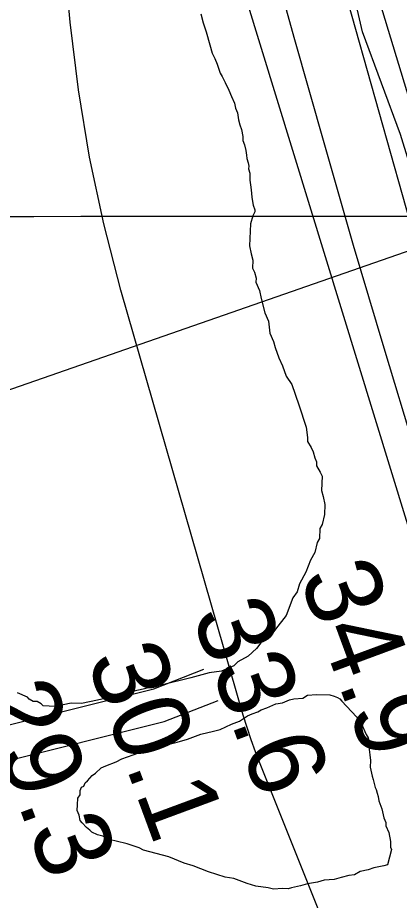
# Model space of a CAD drawing. Extents: x 3297753 to 3335611, y 652252 to 677623.
# Drawn here: x 3307885 to 3308219, y 672189 to 672962 of the extents above; entities that cross this region are included whole.
import ezdxf

# ---------------------------------------------------------------- set-up
doc = ezdxf.new("R2010")
doc.units = 0
for name, color, linetype in [('V-GRID-MAJR', 7, 'Continuous'), ('V-RIVR-EDGE', 7, 'Continuous'), ('V-RIVR-RANG', 7, 'Continuous'), ('V-ROAD-CNTR', 7, 'Continuous'), ('V-RRAP-FSHR', 7, 'Continuous'), ('V-SITE-VEGE', 7, 'Continuous'), ('V-TOPO-MAJR', 7, 'Continuous'), ('V-TOPO-MINR', 7, 'Continuous')]:
    doc.layers.add(name, color=color, linetype=linetype)

msp = doc.modelspace()

# ---------------------------------------------------------------- linework, layer by layer
at = {"layer": 'V-GRID-MAJR'}
msp.add_spline([(3301861.41, 672784.17), (3307118.42, 672787.61), (3312375.44, 672791.81), (3317632.45, 672796.78), (3322889.47, 672802.52), (3328146.48, 672809.02), (3333403.5, 672816.28)], degree=3, dxfattribs=at)
at = {"layer": 'V-RIVR-EDGE'}
msp.add_spline([(3307850.62, 675821), (3307850.75, 675819.26), (3307852.36, 675798.53), (3307852.34, 675791.07), (3307856.9, 675791.47), (3307860.2, 675784), (3307858.08, 675766.6), (3307858.03, 675745.87), (3307859.68, 675743.8), (3307863.41, 675742.96), (3307863.4, 675739.64), (3307862.94, 675720.99), (3307866.19, 675694.04), (3307864.47, 675668.35), (3307864.85, 675653.43), (3307866.04, 675632.29), (3307865.98, 675608.25), (3307860.93, 675578), (3307855.03, 675536.15), (3307852.01, 675490.98), (3307848.61, 675457.42), (3307845.62, 675420.95), (3307843.09, 675401.89), (3307841.81, 675387.8), (3307842.17, 675364.59), (3307841.69, 675337.23), (3307844.13, 675320.65), (3307845.74, 675299.92), (3307848.96, 675263.02), (3307851.37, 675230.27), (3307851.72, 675204.99), (3307854.14, 675179.28), (3307856.98, 675153.99), (3307856.53, 675138.24), (3307855.69, 675135.76), (3307856.07, 675118.35), (3307855.63, 675111.72), (3307854.35, 675095.97), (3307852.65, 675077.74), (3307852.18, 675054.11), (3307855.44, 675031.72), (3307862.38, 674991.5), (3307864.8, 674962.48), (3307868.44, 674926), (3307870.05, 674906.1), (3307872.46, 674875.01), (3307874.08, 674859.25), (3307876.52, 674843.5), (3307878.94, 674816.13), (3307882.53, 674757.68), (3307886.15, 674712.5), (3307885.71, 674704.21), (3307884.45, 674697.99), (3307884.44, 674691.78), (3307887.31, 674680.16), (3307887.28, 674668.97), (3307887.26, 674658.2), (3307885.58, 674651.15), (3307881.01, 674644.12), (3307881, 674639.97), (3307886.35, 674626.28), (3307890.03, 674605.55), (3307895.77, 674578.59), (3307899.43, 674550.81), (3307909.27, 674510.58), (3307914.59, 674481.97), (3307918.25, 674453.78), (3307918.22, 674440.51), (3307919.86, 674433.88), (3307927.3, 674423.08), (3307927.28, 674417.7), (3307927.25, 674404.02), (3307928.48, 674400.28), (3307931.78, 674393.23), (3307935.06, 674376.64), (3307944.54, 674357.55), (3307954.85, 674337.22), (3307963.92, 674316.06), (3307975.42, 674271.68), (3307986.49, 674225.23), (3308000.06, 674178.77), (3308007.44, 674148.91), (3308015.22, 674108.27), (3308020.53, 674078.42), (3308024.25, 674072.19), (3308025.04, 674059.34), (3308025.41, 674039.44), (3308027.79, 673997.16), (3308030.63, 673971.46), (3308027.69, 673955.3), (3308027.24, 673943.28), (3308027.64, 673935.82), (3308029.69, 673925.45), (3308035.46, 673911.76), (3308035.42, 673899.32), (3308034.12, 673873.21), (3308036.13, 673851.24), (3308038.54, 673818.91), (3308040.98, 673799), (3308046.76, 673788.21), (3308050.46, 673778.26), (3308048.79, 673772.46), (3308048.76, 673761.27), (3308053.68, 673740.53), (3308060.66, 673711.09), (3308069.7, 673678.73), (3308069.66, 673665.06), (3308067.15, 673653.46), (3308067.55, 673650.14), (3308072.94, 673649.3), (3308077.91, 673648.87), (3308079.98, 673646.38), (3308086.52, 673608.64), (3308091.84, 673582.1), (3308104.58, 673536.48), (3308114.83, 673495), (3308121.38, 673461), (3308123.83, 673446.07), (3308127.95, 673436.12), (3308140.31, 673406.24), (3308148.95, 673377.21), (3308153.04, 673357.72), (3308158.34, 673321.23), (3308169, 673273.12), (3308189.1, 673188.1), (3308196.88, 673150.37), (3308207.96, 673103.92), (3308212.04, 673079.45), (3308214.06, 673059.97), (3308216.51, 673045.04), (3308218.98, 673035.91), (3308226, 673025.53), (3308228.46, 673015.99), (3308228.43, 673002.32), (3308230.49, 672996.92), (3308235.04, 672992.77), (3308235.02, 672984.48), (3308237.47, 672972.87), (3308241.99, 672953.37), (3308247.32, 672933.05), (3308253.9, 672910.65), (3308257.61, 672901.53), (3308263.8, 672890.32), (3308276.17, 672865), (3308277.39, 672856.3), (3308278.62, 672850.08), (3308283.16, 672844.26), (3308286.05, 672839.7), (3308286.04, 672832.24), (3308285.59, 672818.97), (3308288.47, 672812.33), (3308293.83, 672800.3), (3308303.72, 672777.89), (3308309.9, 672762.54), (3308316.07, 672743.05), (3308316.44, 672725.64), (3308318.1, 672723.15), (3308323.06, 672717.33), (3308327.59, 672706.13), (3308331.69, 672690.37), (3308330.84, 672679.6), (3308330.4, 672672.14), (3308332.46, 672667.16), (3308337.42, 672658.44), (3308343.59, 672642.67), (3308347.7, 672625.26), (3308355.91, 672595.39), (3308355.89, 672584.62), (3308357.53, 672579.64), (3308362.07, 672570.92), (3308366.61, 672563.45), (3308376.07, 672534), (3308399.56, 672478.4), (3308411.51, 672452.67), (3308418.52, 672435.25), (3308421.79, 672418.66), (3308423.01, 672409.95), (3308425.49, 672403.73), (3308428.79, 672397.5), (3308430.01, 672387.55), (3308434.95, 672375.52), (3308444.41, 672344.83), (3308450.58, 672326.99), (3308456.78, 672320.76), (3308459.66, 672312.87), (3308465.4, 672287.99), (3308467.43, 672268.09), (3308473.18, 672249.01), (3308476.05, 672236.57), (3308485.95, 672214.16), (3308490.05, 672198.81), (3308495.86, 672201.7), (3308496.67, 672193), (3308499.08, 672161.9), (3308505.23, 672134.53), (3308513.87, 672107.57), (3308522.52, 672084.75), (3308527.9, 672082.25), (3308536.2, 672087.2), (3308540.76, 672086.78), (3308539.51, 672083.88), (3308535.76, 672077.67), (3308534.91, 672067.73), (3308534.47, 672059.44), (3308531.96, 672050.74), (3308533.2, 672047.42), (3308536.91, 672037.88), (3308550.93, 672008.42), (3308564.93, 671974.39), (3308569.87, 671959.46), (3308576.49, 671954.88), (3308585.14, 671932.48), (3308595.86, 671910.49), (3308604.94, 671895.13), (3308605.76, 671888.49), (3308607.82, 671885.17), (3308610.71, 671881.02), (3308616.47, 671862.77), (3308627.6, 671838.7), (3308640.39, 671816.29), (3308660.99, 671765.26), (3308672.95, 671740.77), (3308685.32, 671715.46), (3308698.53, 671692.21), (3308700.17, 671685.58), (3308711.29, 671658.19), (3308728.21, 671627.9), (3308743.07, 671602.99), (3308758.34, 671575.6), (3308771.97, 671554.84), (3308775.27, 671548.61), (3308783.11, 671536.16), (3308790.54, 671522.88), (3308793.43, 671519.55), (3308797.16, 671517.06), (3308801.29, 671511.24), (3308803.76, 671502.95), (3308810.8, 671502.1), (3308815.77, 671499.19), (3308833.53, 671474.28), (3308845.09, 671458.5), (3308857.08, 671443.55), (3308870.72, 671429.01), (3308882.71, 671418.61), (3308908.77, 671397), (3308930.27, 671375.39), (3308944.33, 671361.26), (3308952.58, 671346.74), (3308960.43, 671336.77), (3308966.22, 671331.78), (3308972.85, 671328.86), (3308985.64, 671307.28), (3309001.75, 671282.37), (3309010.84, 671271.57), (3309010.83, 671268.25), (3309008.34, 671266.19), (3309011.64, 671262.03), (3309018.66, 671250.83), (3309024.85, 671237.13), (3309035.15, 671212.24), (3309059.5, 671169.07), (3309066.5, 671150.82), (3309067.71, 671140.45), (3309071.85, 671135.88), (3309077.22, 671128.41), (3309078.45, 671123.02), (3309078.43, 671117.63), (3309082.15, 671111.4), (3309089.15, 671092.73), (3309098.63, 671073.23), (3309111.41, 671045.01), (3309116.36, 671032.15), (3309123.35, 671011), (3309128.7, 670995.65), (3309133.23, 670984.86), (3309143.97, 670967.42), (3309159.66, 670945.42), (3309169.17, 670933.37), (3309181.99, 670924.22), (3309188.19, 670917.16), (3309197.69, 670902.22), (3309217.1, 670874.81), (3309231.57, 670859.03), (3309239.82, 670845.33), (3309244.79, 670840.76), (3309252.23, 670835.35), (3309260.51, 670831.18), (3309275.4, 670817.06), (3309282.43, 670810.41), (3309290.69, 670800.02), (3309303.1, 670788.39), (3309315.92, 670775.51), (3309335.34, 670751), (3309344.42, 670736.47), (3309351.03, 670726.51), (3309360.13, 670721.51), (3309375.84, 670704.9), (3309390.72, 670688.69), (3309403.11, 670668.77), (3309415.49, 670646.77), (3309426.65, 670635.14), (3309442.78, 670618.52), (3309454.34, 670603.15), (3309462.18, 670588.63), (3309470.85, 670575.34), (3309476.63, 670563.31), (3309487.39, 670558.31), (3309488.62, 670554.57), (3309489.44, 670550.84), (3309494.82, 670544.2), (3309506.81, 670533.39), (3309523.77, 670518.84), (3309529.95, 670505.98), (3309538.6, 670484.82), (3309549.72, 670453.7), (3309551.35, 670440.85), (3309555.47, 670430.89), (3309568.67, 670408.89), (3309577.35, 670396.02), (3309581.47, 670386.48), (3309581.46, 670383.16), (3309578.55, 670379.85), (3309576.88, 670374.88), (3309582.24, 670364.09), (3309594.61, 670336.71), (3309604.49, 670308.91), (3309606.94, 670296.06), (3309614.38, 670284.85), (3309627.18, 670266.99), (3309635.46, 670261.59), (3309639.18, 670259.92), (3309638.74, 670249.97), (3309639.54, 670236.29), (3309641.18, 670228), (3309644.89, 670221.36), (3309656.46, 670208.06), (3309664.31, 670195.61), (3309663.46, 670188.15), (3309663.84, 670176.13), (3309667.96, 670166.17), (3309673.34, 670159.94), (3309684.07, 670142.92), (3309690.66, 670126.33), (3309700.14, 670102.68), (3309716.65, 670076.52)], degree=3, dxfattribs=at)
at = {"layer": 'V-RIVR-RANG'}
msp.add_line((3307493.39, 672503.23), (3308797.09, 672955.76), dxfattribs=at)
at = {"layer": 'V-ROAD-CNTR'}
for points in [[(3307655.66, 672322.75), (3307726.53, 672325.37), (3307861.68, 672338.91), (3308003.94, 672374.33), (3308047.69, 672391.49)], [(3307659.66, 672292.88), (3307728.59, 672295.43), (3307866.83, 672309.28), (3308013.08, 672345.69), (3308060.3, 672364.22)]]:
    msp.add_lwpolyline(points, dxfattribs=at)
at = {"layer": 'V-RRAP-FSHR'}
msp.add_lwpolyline([(3308906.95, 671322.55), (3308835.2, 671388.92), (3308790.02, 671437.53), (3308750.4, 671492.94), (3308721.46, 671549.01), (3308666.58, 671639.8), (3308617.41, 671744.82), (3308562.65, 671871.82), (3308511.44, 671991.88), (3308477.13, 672082.74), (3308422.95, 672271.02), (3308384.31, 672393.55), (3308351.33, 672486.79), (3308320.78, 672583.54), (3308284.41, 672679), (3308253.28, 672753.15), (3308220.18, 672859.88), (3308186.89, 672949.86), (3308152.27, 673100.42)], dxfattribs=at)
at = {"layer": 'V-SITE-VEGE'}
for points in [[(3308045.13, 672965.45), (3308047.24, 672957.56), (3308049.91, 672949.65), (3308053.08, 672938.36), (3308055.19, 672931.02), (3308057.36, 672926.49), (3308059.52, 672921.4), (3308062.19, 672913.49), (3308063.82, 672910.66), (3308066.54, 672905.55), (3308069.79, 672898.76), (3308071.93, 672893.1), (3308074.64, 672887.44), (3308075.69, 672882.93), (3308077.3, 672878.97), (3308078.31, 672872.78), (3308079.36, 672868.26), (3308080.97, 672864.3), (3308081.98, 672858.11), (3308081.93, 672854.74), (3308083.54, 672850.78), (3308084.58, 672845.71), (3308085.07, 672841.77), (3308085.58, 672838.95), (3308086.63, 672835), (3308087.14, 672832.19)], [(3308087.14, 672832.19), (3308087.1, 672829.94), (3308088.16, 672825.99), (3308088.05, 672819.82), (3308089.06, 672813.62), (3308089.54, 672808.56), (3308090.03, 672804.62), (3308091.03, 672797.86), (3308092.65, 672793.9), (3308092.57, 672792.15), (3308090.66, 672788.7), (3308088.61, 672781.73), (3308087.79, 672762.38), (3308089.25, 672755.27), (3308090.78, 672749.92), (3308090.49, 672742.88), (3308092.1, 672739.29), (3308093.63, 672733.94), (3308093.48, 672730.41), (3308096.7, 672723.23), (3308098.17, 672716.11), (3308101.16, 672703.65), (3308104.38, 672696.46), (3308105.69, 672685.83), (3308108.92, 672678.65), (3308110.45, 672673.29), (3308113.6, 672664.35), (3308116.82, 672657.16), (3308119.96, 672648.22), (3308124.94, 672640.95), (3308131.23, 672623.06), (3308132.77, 672617.71), (3308135.92, 672608.76), (3308137.45, 672603.41), (3308138.84, 672594.54), (3308138.69, 672591.02), (3308141.99, 672585.59), (3308143.6, 672582), (3308145.13, 672576.65), (3308146.74, 672573.05), (3308146.59, 672569.53), (3308149.89, 672564.11), (3308151.5, 672560.51), (3308150.98, 672548.2), (3308152.51, 672542.84), (3308153.97, 672535.73), (3308153.6, 672526.94), (3308151.47, 672518.21), (3308149.56, 672514.77), (3308149.19, 672505.97), (3308147.28, 672502.53), (3308145.15, 672493.81), (3308141.33, 672486.92), (3308137.37, 672476.51), (3308131.64, 672466.18), (3308129.58, 672459.21), (3308125.84, 672454.08), (3308119.89, 672438.47), (3308110.57, 672426.53), (3308106.83, 672421.4), (3308097.73, 672414.73), (3308093.99, 672409.6), (3308086.65, 672402.86), (3308077.64, 672397.96), (3308073.97, 672394.59), (3308063.19, 672389.76), (3308052.56, 672388.45), (3308036.5, 672383.84), (3308011.57, 672377.85), (3308004.45, 672376.39), (3307991.99, 672373.39), (3307984.88, 672371.93), (3307974.17, 672368.85), (3307967.06, 672367.39), (3307954.6, 672364.4), (3307940.37, 672361.47), (3307931.57, 672361.85), (3307917.35, 672358.93), (3307906.79, 672359.37), (3307905.11, 672361.21), (3307901.66, 672363.12), (3307898.14, 672363.26), (3307894.7, 672365.17), (3307893.02, 672367.01), (3307884.37, 672370.9)], [(3308208.76, 672220.06), (3308205.79, 672219.2), (3308196.91, 672217.62), (3308191.94, 672215.88), (3308185.02, 672214.21), (3308180.01, 672211.49), (3308175.08, 672210.72), (3308168.16, 672209.05), (3308162.22, 672207.35), (3308153.38, 672206.74), (3308147.44, 672205.04), (3308138.56, 672203.45), (3308132.62, 672201.75), (3308124.72, 672200.13), (3308121.74, 672199.27), (3308116.86, 672199.48), (3308109, 672198.83), (3308104.16, 672200.02), (3308093.45, 672201.45), (3308085.72, 672203.74), (3308074.16, 672208.14), (3308066.38, 672209.45), (3308051.89, 672213.98), (3308038.42, 672219.44), (3308030.68, 672221.73), (3308017.21, 672227.19), (3307994.95, 672233.03), (3307991.12, 672235.15), (3307980.5, 672238.54), (3307970.81, 672240.91), (3307965.96, 672242.09), (3307959.25, 672245.31), (3307954.41, 672246.49), (3307949.6, 672248.66), (3307947.73, 672250.69), (3307944.88, 672252.77), (3307941.14, 672256.84), (3307939.27, 672258.88), (3307938.5, 672263.81), (3307936.71, 672267.8), (3307936.92, 672272.68), (3307937.17, 672278.55), (3307939.25, 672281.4), (3307939.41, 672285.3), (3307940.51, 672288.19), (3307942.51, 672289.09), (3307943.61, 672291.98), (3307945.65, 672293.85), (3307949.76, 672298.57), (3307952.77, 672300.4), (3307957.87, 672305.08), (3307961.86, 672306.86), (3307970.82, 672310.4), (3307975.83, 672313.13), (3307990.73, 672318.37), (3307995.66, 672319.14), (3308004.62, 672322.67), (3308011.54, 672324.34), (3308024.41, 672327.71), (3308033.33, 672330.27), (3308045.26, 672334.66), (3308056.13, 672337.13), (3308062.08, 672338.84), (3308072.05, 672343.31), (3308079.02, 672345.95), (3308086.06, 672350.55), (3308090.05, 672352.33), (3308095.02, 672354.08), (3308098.04, 672355.91), (3308103, 672357.66), (3308110.99, 672361.24), (3308116.89, 672361.96), (3308122.88, 672364.65), (3308126.83, 672365.46), (3308134.69, 672366.1), (3308138.72, 672368.87), (3308146.57, 672369.52), (3308158.3, 672369.02), (3308162.17, 672367.88), (3308165.06, 672366.78), (3308166.97, 672365.71), (3308168.84, 672363.68), (3308177.26, 672354.51), (3308181.94, 672349.42), (3308185.64, 672344.37), (3308190.11, 672334.39), (3308191.94, 672331.38), (3308192.71, 672326.45), (3308192.59, 672323.52), (3308193.28, 672316.64), (3308194.04, 672311.71), (3308193.8, 672305.85), (3308195.42, 672297.95), (3308196.27, 672294.98), (3308197.94, 672288.05), (3308198.83, 672286.06), (3308199.69, 672283.09), (3308200.54, 672280.11), (3308201.35, 672276.16), (3308203.99, 672269.2), (3308205.61, 672261.3)], [(3308205.61, 672261.3), (3308207.4, 672257.31), (3308207.28, 672254.38), (3308209.96, 672248.39), (3308211.58, 672240.49), (3308211.38, 672235.61), (3308212.27, 672233.61), (3308208.76, 672220.06)]]:
    msp.add_lwpolyline(points, dxfattribs=at)
at = {"layer": 'V-TOPO-MAJR'}
msp.add_lwpolyline([(3307928.64, 673656.58), (3308127.39, 672943.15), (3308152.91, 672852.91), (3308178.89, 672762.8), (3308205.57, 672672.89), (3308232.71, 672583.13), (3308284.67, 672413.69), (3308286.24, 672408.76), (3308287.88, 672403.86), (3308289.64, 672398.99), (3308291.47, 672394.15), (3308347.82, 672249.98), (3308378.37, 672173.29), (3308409.59, 672096.87), (3308441.8, 672020.86), (3308474.68, 671945.12), (3308677.49, 671486.09), (3308687.08, 671465.01), (3308696.97, 671444.08), (3308707.31, 671423.37), (3308717.96, 671402.8), (3309100.94, 670844.39)], dxfattribs=at)
at = {"layer": 'V-TOPO-MINR'}
for points in [[(3307885.1, 673628.71), (3308253.74, 672428.93), (3308259.15, 672412.04), (3308264.83, 672395.25), (3308270.91, 672378.6), (3308277.25, 672362.04), (3308604.36, 671538.51), (3308612.31, 671519.09), (3308620.53, 671499.8), (3308629.16, 671480.69), (3308638.06, 671461.69), (3308647.21, 671442.81)], [(3307996.51, 673604.08), (3308313.7, 672481.59), (3308322.7, 672450.88), (3308332.07, 672420.29), (3308342.02, 672389.88), (3308352.36, 672359.59), (3308391.6, 672248.03), (3308422.69, 672162.39), (3308454.9, 672077.19), (3308488.81, 671992.64), (3308523.84, 671908.53), (3308709.63, 671474.65), (3308714.03, 671464.7), (3308718.57, 671454.81), (3308723.34, 671445.02), (3308728.25, 671435.31), (3309049.7, 670968.67)], [(3308494.38, 671397.36), (3308411.05, 671569.9), (3308360.02, 671678.4), (3308310.5, 671787.56), (3308263.23, 671897.71), (3308217.46, 672008.53), (3308097.17, 672308.51), (3308093.11, 672319.11), (3308089.26, 672329.78), (3308085.74, 672340.56), (3308082.43, 672351.42), (3307975.12, 672723.56), (3307960.16, 672781.52), (3307947.4, 672839.9), (3307937.92, 672898.9), (3307930.65, 672958.31), (3307927.05, 672996.6)], [(3308199.62, 672984.21), (3308359.3, 672458.09), (3308363.18, 672445.74), (3308367.24, 672433.44), (3308371.54, 672421.22), (3308376, 672409.07), (3308708.9, 671530.27), (3308713.22, 671519.07), (3308717.65, 671507.9), (3308722.21, 671496.79), (3308726.87, 671485.72), (3308735.73, 671465.05), (3308736.7, 671462.96), (3308737.04, 671462.27), (3308741.12, 671454.42), (3308742.88, 671451.2), (3308744.73, 671448.03), (3308746.71, 671444.95), (3308748.77, 671441.91), (3308750.9, 671438.91), (3308753.03, 671435.92), (3308755.16, 671432.93), (3308757.29, 671429.93), (3308898.94, 671231.74)]]:
    msp.add_lwpolyline(points, dxfattribs=at)

# ---------------------------------------------------------------- texts
at = {"layer": 'V-RIVR-RANG'}
for s, p in [('34.9', (3308130.99, 672472.42)), ('33.6', (3308036.75, 672438.96)), ('30.1', (3307944.51, 672400.06)), ('29.3', (3307849.99, 672367.35))]:
    msp.add_text(s, height=67, rotation=290.30833, dxfattribs=at).set_placement(p)

doc.saveas('drawing.dxf')
